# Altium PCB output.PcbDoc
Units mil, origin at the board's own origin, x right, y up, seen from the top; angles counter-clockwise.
Board outline 1336.9 x 1336.9 mil, 2 copper layers (Top Layer, Bottom Layer); 6 components, 7 nets, 22 pads, 0 vias.
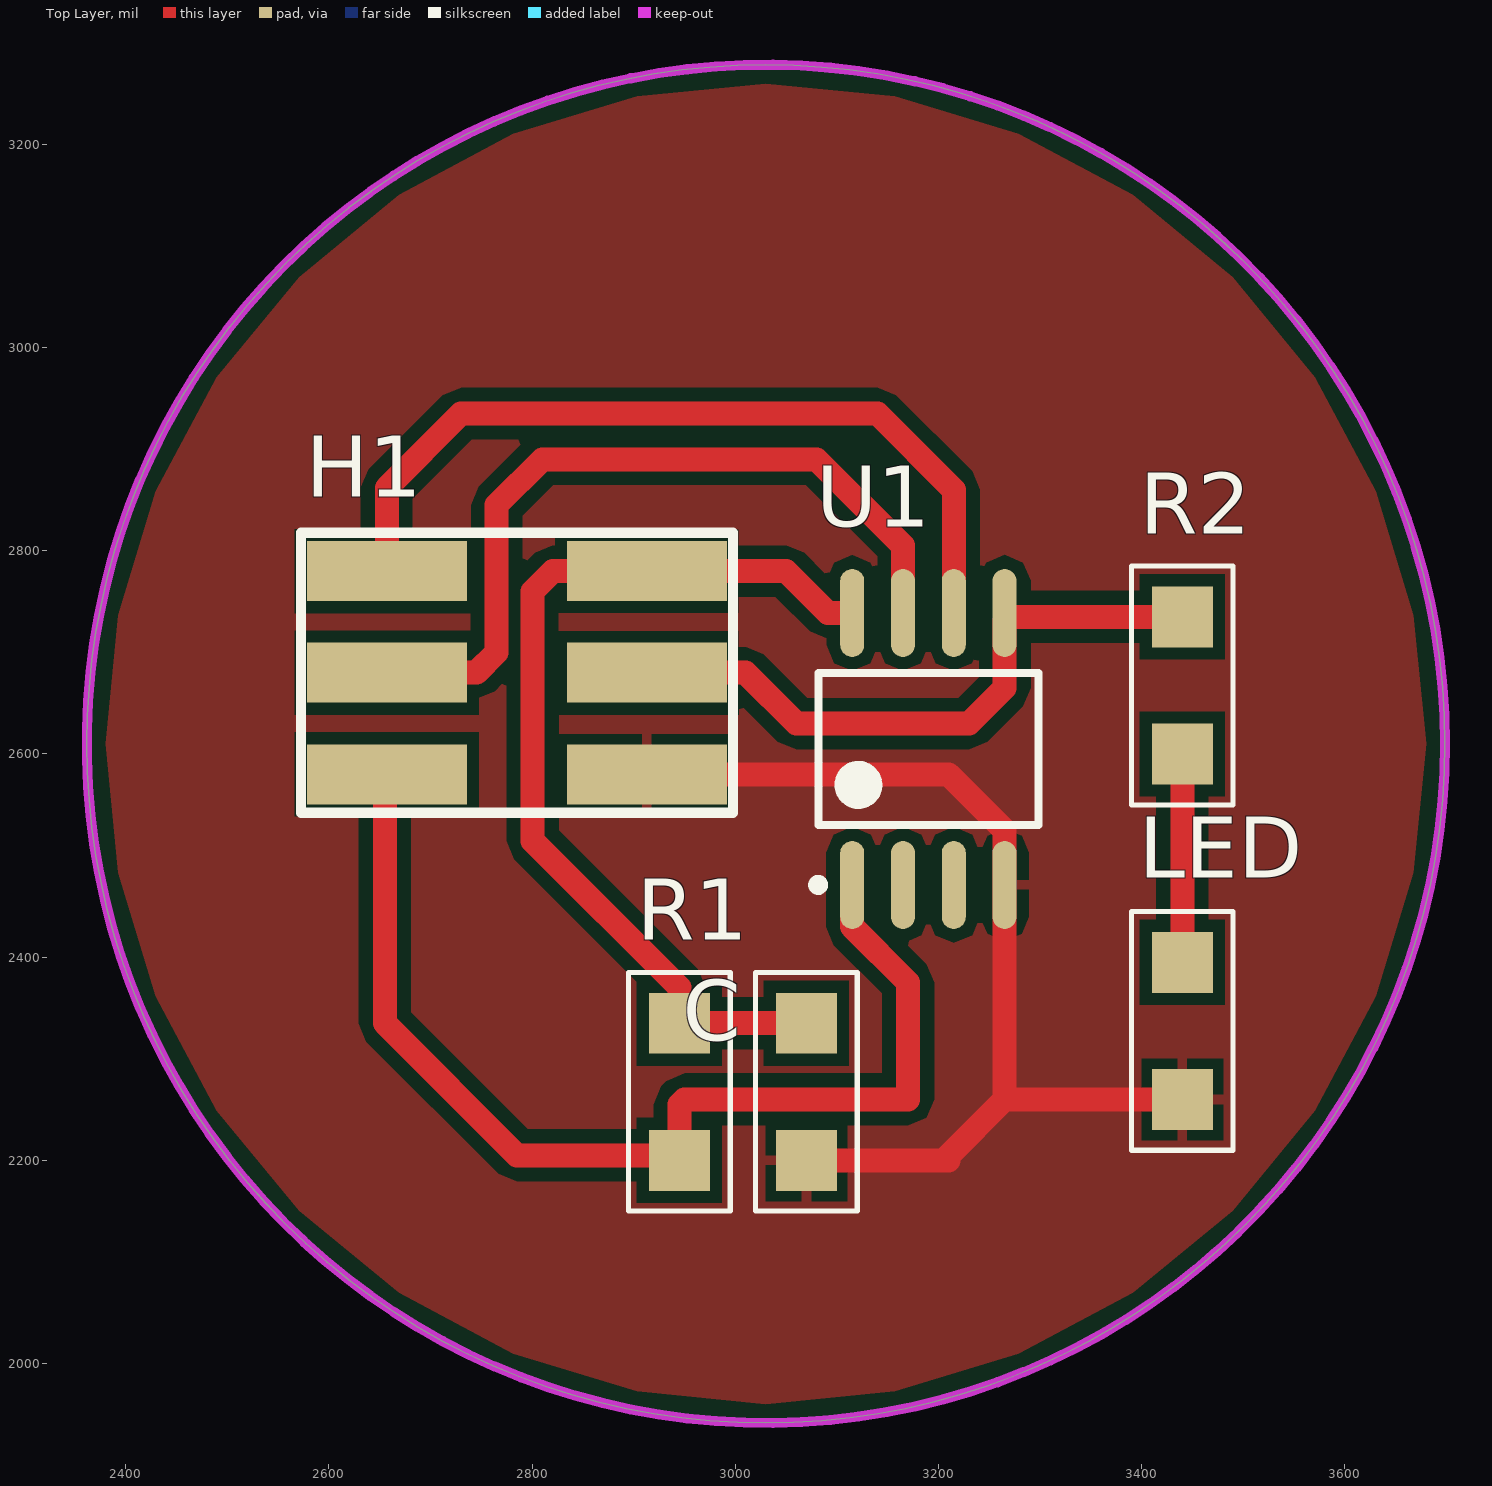
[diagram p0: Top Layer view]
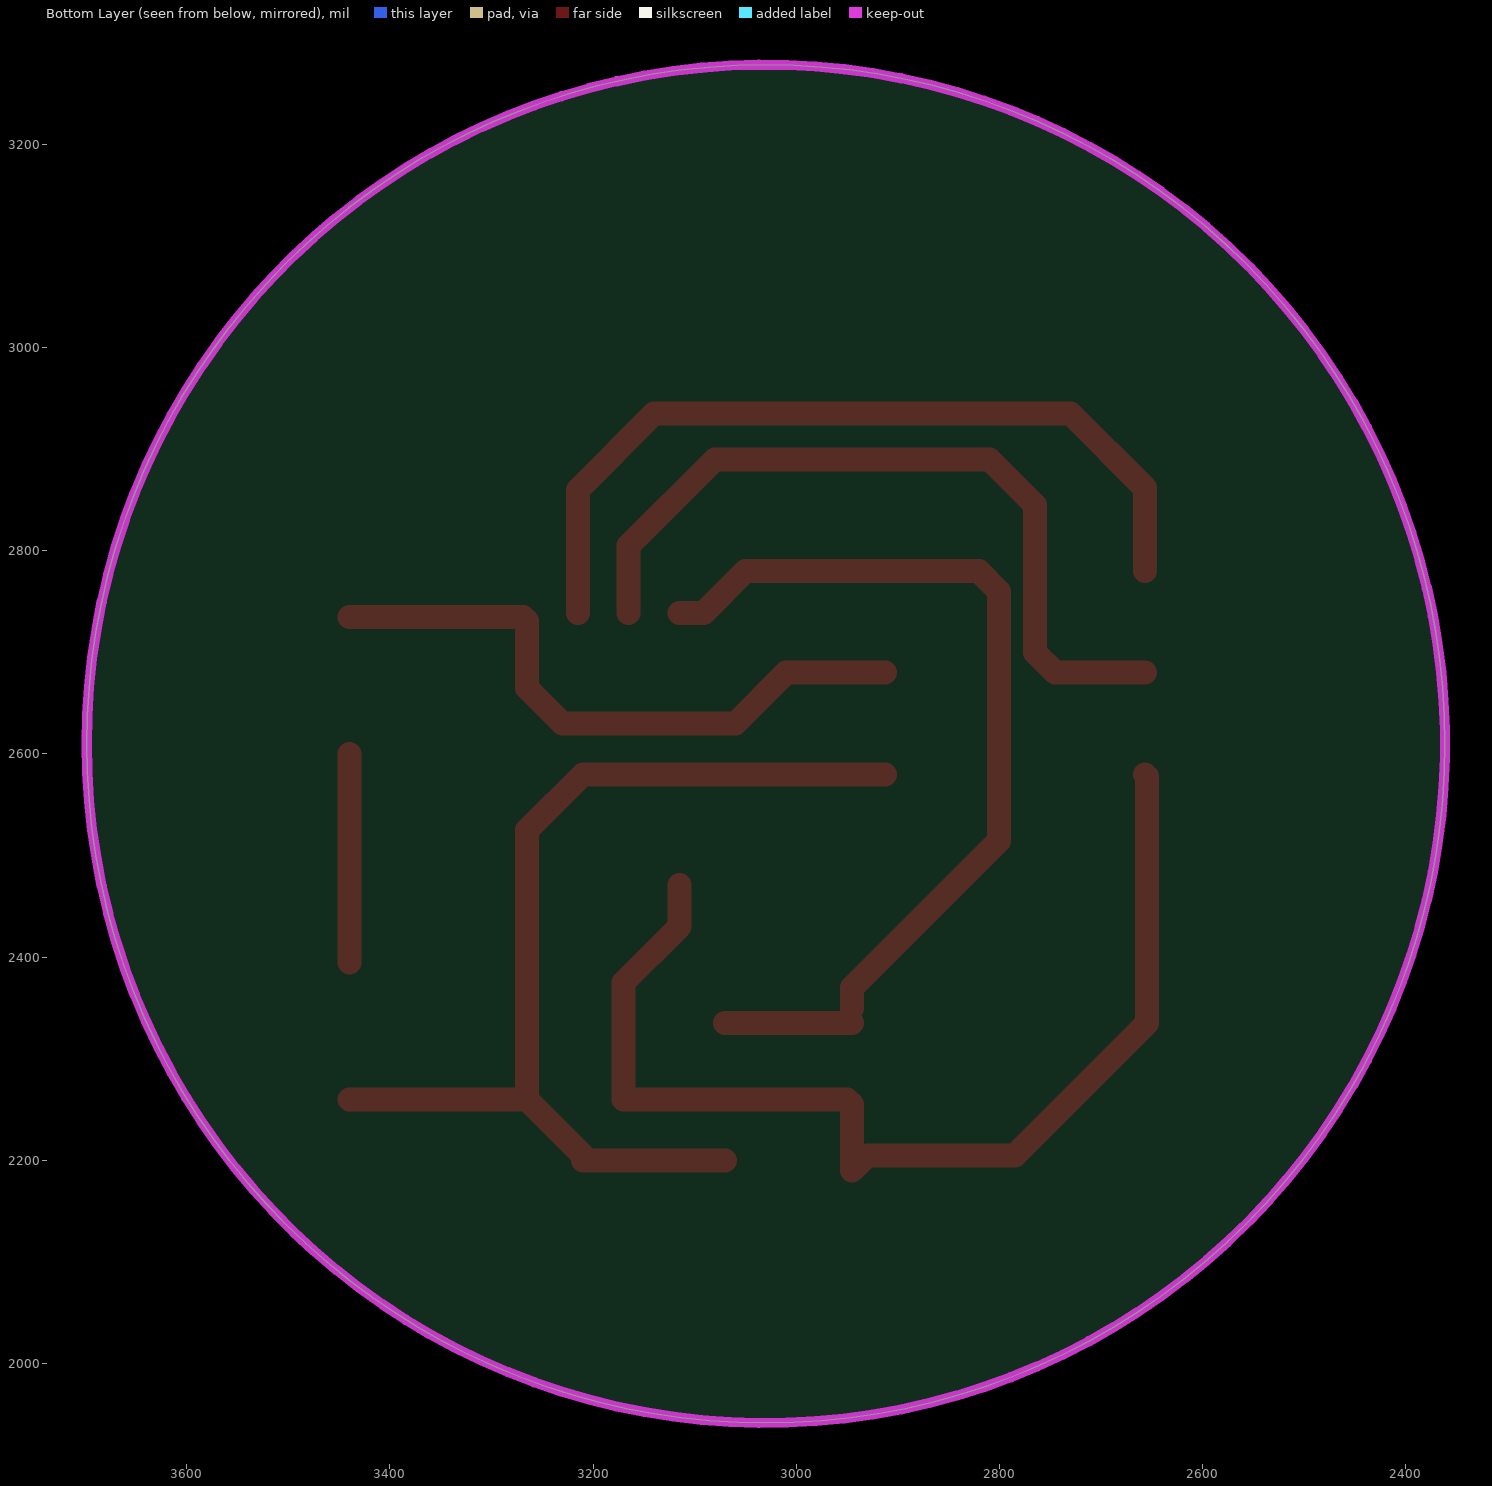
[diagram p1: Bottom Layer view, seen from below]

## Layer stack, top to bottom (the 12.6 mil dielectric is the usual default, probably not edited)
Top Solder: solder mask 0.4, Solder Resist, Dk 3.5
Top Layer: signal copper 1.4
Dielectric 1: dielectric 12.6, FR-4, Dk 4.8
Bottom Layer: signal copper 1.4
Bottom Solder: solder mask 0.4, Solder Resist, Dk 3.5

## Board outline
2361.55,2610 cw(c3030,2610) 3030,3278.45 cw(c3030,2610) 3698.45,2610 cw(c3030,2610) 3030,1941.55 cw(c3030,2610)

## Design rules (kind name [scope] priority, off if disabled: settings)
Clearance [All] p1: gap=11.81
PolygonConnect [All] p1: connectstyle=Relief reliefconductorwidth=10 reliefentries=4 polygonreliefangle="90 Angle" airgapwidth=10
RoutingLayers [All] p1: top layer_v5=TRUE bottom layer_v5=FALSE
RoutingVias [All] p1: holewidth=28 width=50 viastyle="Through Hole" minholewidth=28 minwidth=50 maxholewidth=28 maxwidth=50
SolderMaskExpansion [All] p1: expansion=4
Width [All] p1: maxlimit=23.62 minlimit=15.75 preferedwidth=23.62
29 further rules are at their usual default settings.

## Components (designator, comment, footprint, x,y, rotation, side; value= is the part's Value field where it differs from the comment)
C "1UF" 1206C-GENERIC 3070,2335 r270 top
H1 "H" "smdHeader 2x3" 2785,2680 r180 top
LED "" 1206C-GENERIC 3440,2395 r270 top
R1 "10k" 1206C-GENERIC 2945,2335 r270 top
R2 "1k" 1206C-GENERIC 3440,2735 r270 top
U1 "ATtiny45-20SU" 8S2_N 3190,2605 r90 top

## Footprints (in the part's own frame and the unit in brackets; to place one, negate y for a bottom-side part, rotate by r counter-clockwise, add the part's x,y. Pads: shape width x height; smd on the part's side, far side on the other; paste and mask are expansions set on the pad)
8S2_N [mm] "SOP, 8-Leads, Body 5.3x5.3mm, Pitch 1.27mm, IPC Medium Density"
  oval 2.2x0.6 smd: 1(-3.4,1.905) 2(-3.4,0.635) 3(-3.4,-0.635) 4(-3.4,-1.905) 5(3.4,-1.905) 6(3.4,-0.635) 7(3.4,0.635) 8(3.4,1.905)
  silkscreen extent -3.52,-2.75 1.9,2.88, body extent -2.73,-2.75 2.73,2.75, height 2.16
1206C-GENERIC [mil]
  rect 60x60 smd: 1(0,0) 2(135,0)
  silkscreen extent -50,-50 185,50, body extent -8,-29 147,29, height 46
"smdHeader 2x3" [mm]
  rect 4x1.5 smd: 0(-3.25,2.54) 1(-3.25,0) 2(-3.25,-2.54) 3(3.25,2.54) 4(3.25,0) 5(3.25,-2.54)
  silkscreen extent -5.4,-3.5 5.4,3.5

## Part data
C LED R1 R2: library part 1206C-10U-35V-X7R, "GENERIC CAPACITOR NON POLARISED 1206"
H1: library part "smadheader 2x3"
U1: "Low Power tinyAVR® 8-Bit Microcontroller, 4K Flash Memory, 20MHz, Industrial Temperature, 8-Lead SOIC, Pb-Free"

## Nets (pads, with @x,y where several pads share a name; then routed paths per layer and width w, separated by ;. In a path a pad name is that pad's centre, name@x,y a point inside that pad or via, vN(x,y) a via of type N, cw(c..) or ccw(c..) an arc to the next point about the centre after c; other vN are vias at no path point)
GND: C.2 H1.0 LED.2 U1.4 | length 1037.6
  Top Layer w23.62: H1.0 3210,2580 3265,2525 U1.4 3265,2260 ; C.2 3210,2200 3210,2205 3265,2260 ; LED.2 3265,2260
NetH1_1: H1.1 R2.1 U1.5 | length 630
  Top Layer w23.62: H1.1 3010,2680 3060,2630 3230,2630 3265,2665 3265,2731.14 3268.86,2735 R2.1
NetH1_3: H1.3 R1.2 U1.1 | length 1121.9
  Top Layer w23.62: H1.3 2655,2577.95 2655,2335 2785,2205 2930,2205 2945,2190 2945,2255 2950,2260 3170,2260 3170,2375 3115,2430 U1.1
NetH1_4: H1.4 U1.7 | length 781.2
  Top Layer w23.62: H1.4 2745,2680 2765,2700 2765,2845 2810,2890 3080,2890 3165,2805 U1.7
NetH1_5: H1.5 U1.6 | length 822.4
  Top Layer w23.62: H1.5 2657.05,2862.05 2730,2935 3140,2935 3215,2860 U1.6
NetLED_1: LED.1 R2.2 | length 205
  Top Layer w23.62: LED.1 R2.2
VCC: C.1 H1.2 R1.1 U1.8 | length 934.8
  Top Layer w23.62: R1.1 C.1 ; R1.1@2945,2350 2945,2370 2800.43,2514.57 2800.43,2760 2820.43,2780 H1.2 3050,2780 3091.14,2738.86 U1.8
pads on no net: U1.2 U1.3

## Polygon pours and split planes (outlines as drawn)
GND on Top Layer "NONET_L01_P-001" (solid, pour order 0): 2778.28,3229.24 3030,3310.3 3250,3278.45 3560,3080 3663.65,2822.87 3710,2598.45 3649.24,2358.28 3590,2245 3484.84,2120.16 3372.5,2027.5 3175.37,1957.55 2975,1941.55 2778.28,1990.76 2640,2057.05 2525,2172.05 2389.68,2418.13 2361.55,2771.37 2476.44,3031.44 2640,3195

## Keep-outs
Keep-Out Layer:
  circle w10: c3030,2610 r668.45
